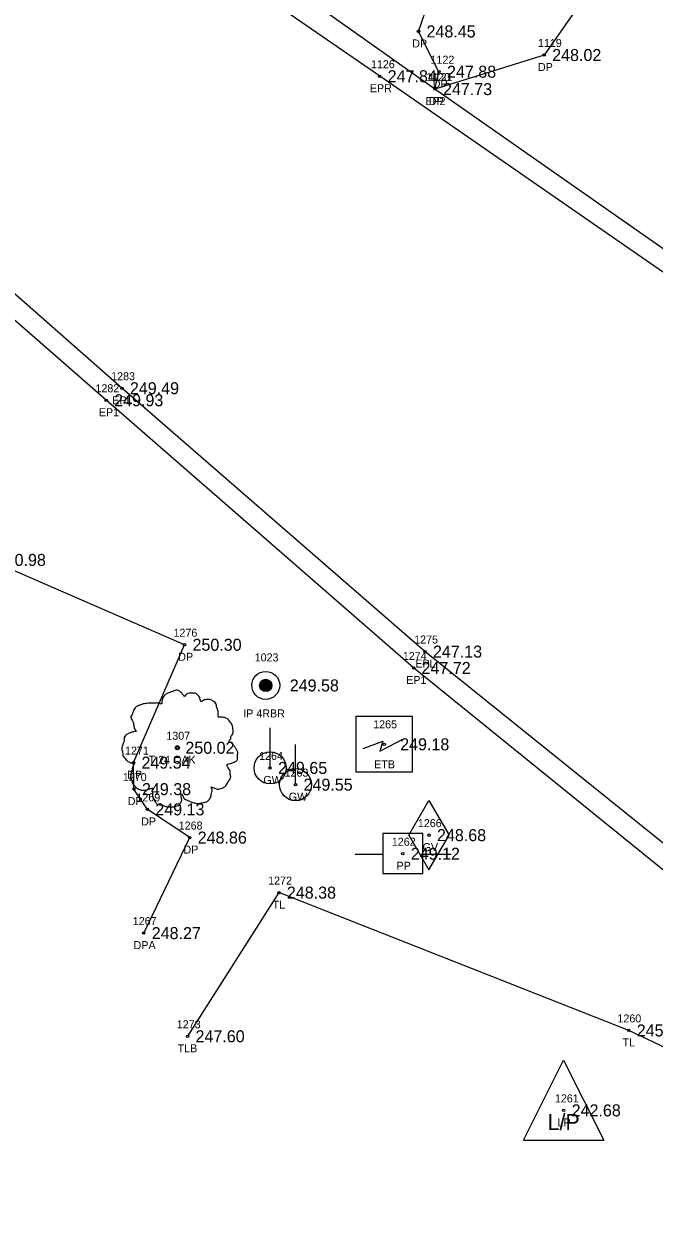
# Model space of a CAD drawing. Extents: x 1961231 to 1962574, y 799865 to 801120.
# Drawn here: x 1962101.5 to 1962180.3, y 800312.9 to 800461.9 of the extents above; entities that cross this region are included whole.
import ezdxf

# ---------------------------------------------------------------- set-up
doc = ezdxf.new("R2010")
doc.units = 0
for name, color, linetype in [('RD_EX_Driveway', 7, 'Continuous'), ('RD_EX_Driveway_txCode', 7, 'Continuous'), ('RD_EX_DV_Prop_txCode', 7, 'Continuous'), ('RD_EX_DV_PropPin', 7, 'Continuous'), ('RD_EX_Road', 7, 'Continuous'), ('RD_EX_Road_txCode', 7, 'Continuous'), ('RD_EX_TX_Driveway_ELEV', 7, 'Continuous'), ('RD_EX_TX_DV_Prop_ELEV', 7, 'Continuous'), ('RD_EX_TX_Road_ELEV', 7, 'Continuous'), ('RD_EX_TX_UT_ELEV', 7, 'Continuous'), ('RD_EX_TX_VEG_ELEV', 7, 'Continuous'), ('RD_EX_UT', 7, 'Continuous'), ('RD_EX_UT_txCode', 7, 'Continuous'), ('RD_EX_VEG', 7, 'Continuous'), ('RD_EX_VEG_txCode', 7, 'Continuous'), ('RD_HC_Survey_ELEV', 7, 'Continuous'), ('RD_SMD_Locator', 7, 'Continuous')]:
    doc.layers.add(name, color=color, linetype=linetype)

msp = doc.modelspace()

# ---------------------------------------------------------------- linework, layer by layer
at = {"layer": 'RD_EX_Driveway'}
for points in [[(1962171.38, 800493.75), (1962163.68, 800485.64), (1962177.97, 800474.42), (1962166.53, 800458.03), (1962152.89, 800453.77), (1962153.39, 800455.94), (1962150.83, 800460.97), (1962153.43, 800468.5), (1962117.51, 800493.93), (1962107.43, 800485.96)], [(1962116.51, 800348.31), (1962122.25, 800360.25), (1962116.96, 800363.77), (1962115.29, 800366.3), (1962115.23, 800369.61), (1962121.6, 800384.34), (1962097.15, 800394.94), (1962048.58, 800416.05), (1962040.61, 800398.11), (1962038.55, 800396.32), (1962035.9, 800396.16), (1962023.43, 800402.56), (1962019.98, 800406.52), (1962018.15, 800411.16)]]:
    msp.add_lwpolyline(points, dxfattribs=at)
at = {"layer": 'RD_EX_DV_PropPin'}
for p, q in [((1962131.02, 800379.07), (1962131.02, 800379.46)), ((1962131.05, 800378.97), (1962131.05, 800379.56)), ((1962131.09, 800378.9), (1962131.09, 800379.63)), ((1962131.12, 800378.84), (1962131.12, 800379.69)), ((1962131.16, 800378.79), (1962131.16, 800379.74)), ((1962131.19, 800378.75), (1962131.19, 800379.78)), ((1962131.23, 800378.71), (1962131.23, 800379.82)), ((1962131.26, 800378.68), (1962131.26, 800379.85)), ((1962131.3, 800378.66), (1962131.3, 800379.87)), ((1962131.33, 800378.63), (1962131.33, 800379.9)), ((1962131.37, 800378.61), (1962131.37, 800379.92)), ((1962131.4, 800378.59), (1962131.4, 800379.94)), ((1962131.44, 800378.57), (1962131.44, 800379.96)), ((1962131.47, 800378.56), (1962131.47, 800379.97)), ((1962131.51, 800378.54), (1962131.51, 800379.99)), ((1962131.54, 800378.53), (1962131.54, 800380)), ((1962131.58, 800378.52), (1962131.58, 800380.01)), ((1962131.61, 800378.52), (1962131.61, 800380.01)), ((1962131.65, 800378.51), (1962131.65, 800380.02)), ((1962131.68, 800378.51), (1962131.68, 800380.02)), ((1962131.72, 800378.5), (1962131.72, 800380.03)), ((1962131.75, 800378.5), (1962131.75, 800380.03)), ((1962131.79, 800378.5), (1962131.79, 800380.03)), ((1962131.82, 800378.51), (1962131.82, 800380.02)), ((1962131.86, 800378.51), (1962131.86, 800380.02)), ((1962131.89, 800378.52), (1962131.89, 800380.01)), ((1962131.93, 800378.52), (1962131.93, 800380.01)), ((1962131.96, 800378.53), (1962131.96, 800380)), ((1962132, 800378.54), (1962132, 800379.99)), ((1962132.03, 800378.56), (1962132.03, 800379.97)), ((1962132.07, 800378.57), (1962132.07, 800379.96)), ((1962132.11, 800378.59), (1962132.11, 800379.94)), ((1962132.14, 800378.61), (1962132.14, 800379.92)), ((1962132.18, 800378.63), (1962132.18, 800379.9)), ((1962132.21, 800378.66), (1962132.21, 800379.87)), ((1962132.25, 800378.68), (1962132.25, 800379.85)), ((1962132.28, 800378.71), (1962132.28, 800379.82)), ((1962132.32, 800378.75), (1962132.32, 800379.78)), ((1962132.35, 800378.79), (1962132.35, 800379.74)), ((1962132.39, 800378.84), (1962132.39, 800379.69)), ((1962132.42, 800378.9), (1962132.42, 800379.63)), ((1962132.46, 800378.97), (1962132.46, 800379.56)), ((1962132.49, 800379.07), (1962132.49, 800379.46))]:
    msp.add_line(p, q, dxfattribs=at)
for radius in [1.75, 0.761]:
    msp.add_circle((1962131.75, 800379.26), radius, dxfattribs=at)
at = {"layer": 'RD_EX_Road'}
for points in [[(1962276.74, 800366.53), (1962275.76, 800367.28), (1962226.46, 800400.66), (1962183.05, 800429.73), (1962145.98, 800455.38), (1962104.4, 800484.06), (1962056.77, 800517.94), (1962023.95, 800541.05), (1961991.87, 800563.56), (1961983.89, 800569.94), (1961938.77, 800603.67), (1961913.43, 800623.83), (1961897.73, 800636.17), (1961851.62, 800671.61), (1961815.86, 800699.48), (1961795.77, 800715.49), (1961771.88, 800733.73), (1961750.77, 800750.96), (1961735.63, 800762.82), (1961702.92, 800788.52)], [(1962241.79, 800315.68), (1962238.35, 800317.6), (1962189.92, 800352.69), (1962151.64, 800383.49), (1962113.78, 800416.39), (1962074.11, 800451.29), (1962034.78, 800486.96), (1962017.07, 800503.17), (1961999.46, 800519.25), (1961962.48, 800552.12), (1961937.08, 800573.11), (1961923.19, 800584.9), (1961883.07, 800617.43), (1961838.29, 800653.43), (1961801.42, 800682.57), (1961728.41, 800740.86), (1961722.95, 800745.11), (1961689.13, 800771.93)], [(1962275.76, 800367.28), (1962274.03, 800371.18), (1962275.17, 800373.82), (1962239.93, 800394.94), (1962227.76, 800403.12), (1962207.73, 800416.44), (1962184.45, 800431.68), (1962152.89, 800453.77), (1962107.43, 800485.96), (1962091.52, 800497.24), (1962058.28, 800520.2), (1962027.14, 800543.26), (1961995.14, 800564.69), (1961983.89, 800569.94)], [(1962238.35, 800317.6), (1962235.93, 800316.57), (1962188.31, 800350.58), (1962150.21, 800381.44), (1962111.82, 800414.89), (1962080.07, 800442.59), (1962070.81, 800442.86), (1962050.61, 800440.1), (1962031.05, 800427.32), (1962017.92, 800411.54)]]:
    msp.add_lwpolyline(points, dxfattribs=at)
at = {"layer": 'RD_EX_UT'}
for p, q in [((1962132.29, 800368.95), (1962132.29, 800373.95)), ((1962135.47, 800366.86), (1962135.47, 800371.86)), ((1962149.64, 800360.55), (1962152.14, 800364.88)), ((1962152.14, 800364.88), (1962154.64, 800360.55)), ((1962151.37, 800360.74), (1962146.37, 800360.74)), ((1962146.37, 800360.74), (1962146.37, 800355.74)), ((1962149.64, 800360.55), (1962152.14, 800356.22)), ((1962151.37, 800355.74), (1962151.37, 800360.74)), ((1962152.14, 800356.22), (1962154.64, 800360.55)), ((1962142.93, 800358.18), (1962146.4, 800358.18)), ((1962151.29, 800358.18), (1962154.93, 800358.18)), ((1962146.37, 800355.74), (1962151.37, 800355.74)), ((1962163.96, 800322.43), (1962168.96, 800332.43)), ((1962168.96, 800332.43), (1962173.96, 800322.43)), ((1962163.96, 800322.43), (1962173.96, 800322.43))]:
    msp.add_line(p, q, dxfattribs=at)
msp.add_lwpolyline([(1962143.04, 800368.4), (1962143.04, 800375.4), (1962150.04, 800375.4), (1962150.04, 800368.4)], close=True, dxfattribs=at)
msp.add_lwpolyline([(1962143.93, 800371.39), (1962146.36, 800372.29), (1962146.01, 800371.05), (1962149.06, 800372.64)], dxfattribs=at)
for centre in [(1962132.29, 800368.95), (1962135.47, 800366.86)]:
    msp.add_circle(centre, 2, dxfattribs=at)
at = {"layer": 'RD_EX_VEG'}
msp.add_lwpolyline([(1962226.08, 800312.94), (1962177.09, 800336.15), (1962133.39, 800353.37), (1962121.98, 800335.42)], dxfattribs=at)
for centre, radius in [((1962120.71, 800371.47), 0.25), ((1962120.7, 800371.45), 0.0001)]:
    msp.add_circle(centre, radius, dxfattribs=at)
for points in [[(1962120.85, 800378.64), (1962120.55, 800378.66), (1962120.22, 800378.56), (1962119.97, 800378.46), (1962119.75, 800378.39), (1962119.52, 800378.29), (1962119.22, 800378.11), (1962119, 800377.91), (1962118.87, 800377.66), (1962118.82, 800377.44), (1962118.77, 800377.16), (1962118.77, 800376.99), (1962118.65, 800376.96), (1962118.5, 800376.99), (1962118.25, 800377.06), (1962118, 800377.06), (1962117.75, 800377.06), (1962117.4, 800377.04), (1962117.05, 800377.04), (1962116.77, 800376.99), (1962116.45, 800376.94), (1962116.07, 800376.81), (1962115.72, 800376.69), (1962115.42, 800376.44), (1962115.17, 800375.96), (1962115.05, 800375.61), (1962114.9, 800375.36), (1962115.05, 800374.91), (1962115.22, 800374.56), (1962115.25, 800374.36), (1962115.32, 800373.94), (1962115.42, 800373.71), (1962115.55, 800373.51), (1962115.47, 800373.49), (1962115.1, 800373.44), (1962114.8, 800373.34), (1962114.37, 800373.11), (1962114.15, 800372.89), (1962114.05, 800372.56), (1962114.02, 800372.21), (1962113.92, 800372.01), (1962113.85, 800371.74), (1962113.82, 800371.66), (1962113.77, 800371.34), (1962113.87, 800370.89), (1962113.9, 800370.54), (1962114.02, 800370.31), (1962114.17, 800370.14), (1962114.35, 800369.89), (1962114.75, 800369.66), (1962115.07, 800369.56), (1962115.27, 800369.54), (1962115.1, 800369.04), (1962115.05, 800368.69), (1962114.92, 800368.29), (1962114.92, 800368.21), (1962114.87, 800367.74), (1962115.02, 800367.42), (1962115.1, 800367.04), (1962115.27, 800366.82), (1962115.55, 800366.52), (1962115.87, 800366.29), (1962116.37, 800366.17), (1962116.77, 800366.19), (1962117.35, 800366.37), (1962117.6, 800366.44), (1962117.57, 800366.27), (1962117.6, 800365.89), (1962117.6, 800365.47), (1962117.75, 800365.14), (1962117.85, 800364.87), (1962118, 800364.62), (1962118.32, 800364.39), (1962118.72, 800364.32), (1962119.15, 800364.17), (1962119.6, 800364.09), (1962120.1, 800364.07), (1962120.7, 800364.22), (1962120.97, 800364.34), (1962121.07, 800364.52), (1962121.27, 800364.89), (1962121.22, 800365.12), (1962121.25, 800365.72), (1962121.35, 800365.54), (1962121.52, 800365.19), (1962122.02, 800364.89), (1962122.42, 800364.72), (1962122.9, 800364.57), (1962123.2, 800364.49), (1962123.67, 800364.57), (1962124.05, 800364.64), (1962124.42, 800364.77), (1962124.72, 800365.04), (1962124.9, 800365.32), (1962124.95, 800365.59), (1962125.02, 800365.97), (1962125.07, 800366.14)], [(1962125.07, 800366.14), (1962125, 800366.32), (1962124.95, 800366.57), (1962125.02, 800366.54), (1962125.19, 800366.49), (1962125.47, 800366.37), (1962125.69, 800366.29), (1962126.02, 800366.32), (1962126.29, 800366.42), (1962126.74, 800366.69), (1962127.02, 800367.17), (1962127.29, 800367.57), (1962127.37, 800367.89), (1962127.32, 800368.11), (1962127.29, 800368.61), (1962127.09, 800368.86), (1962127.04, 800368.99), (1962126.94, 800369.39), (1962127.02, 800369.44), (1962127.29, 800369.49), (1962127.67, 800369.61), (1962127.94, 800369.74), (1962128.17, 800369.91), (1962128.24, 800370.14), (1962128.22, 800370.54), (1962128.27, 800370.94), (1962128.19, 800371.09), (1962128.09, 800371.24), (1962128.02, 800371.44), (1962127.87, 800371.59), (1962127.77, 800371.74), (1962127.67, 800371.84), (1962127.54, 800371.99), (1962127.37, 800372.11), (1962127.22, 800372.16), (1962127.17, 800372.31), (1962127.32, 800372.51), (1962127.37, 800372.61), (1962127.39, 800372.84), (1962127.62, 800373.19), (1962127.67, 800373.59), (1962127.62, 800374.01), (1962127.57, 800374.29), (1962127.42, 800374.56), (1962127.22, 800374.81), (1962127.09, 800374.99), (1962126.92, 800375.11), (1962126.59, 800375.24), (1962126.34, 800375.29), (1962125.99, 800375.29), (1962125.79, 800375.34), (1962125.82, 800375.39), (1962125.82, 800375.54), (1962125.82, 800375.81), (1962125.74, 800376.26), (1962125.59, 800376.76), (1962125.59, 800376.79), (1962125.49, 800377.04), (1962125.27, 800377.24), (1962125.09, 800377.34), (1962124.9, 800377.46), (1962124.65, 800377.49), (1962124.35, 800377.49), (1962124.07, 800377.44), (1962123.87, 800377.34), (1962123.7, 800377.21), (1962123.62, 800377.36), (1962123.52, 800377.66), (1962123.47, 800377.81), (1962123.32, 800377.99), (1962123.1, 800378.19), (1962122.65, 800378.31), (1962122.02, 800378.24), (1962121.72, 800378.04), (1962121.57, 800377.86), (1962121.52, 800377.99), (1962121.32, 800378.19), (1962121.22, 800378.36), (1962121.05, 800378.49), (1962120.9, 800378.59), (1962120.8, 800378.64)]]:
    msp.add_spline(points, degree=3, dxfattribs=at)
at = {"layer": 'RD_SMD_Locator'}
for centre in [(1962150.83, 800460.97), (1962166.53, 800458.03), (1962145.98, 800455.38), (1962153.39, 800455.94), (1962152.89, 800453.77), (1962152.89, 800453.77), (1962113.78, 800416.39), (1962111.82, 800414.89), (1962121.6, 800384.34), (1962151.64, 800383.49), (1962150.21, 800381.44), (1962131.75, 800379.26), (1962120.71, 800371.47), (1962146.54, 800371.9), (1962115.23, 800369.61), (1962132.29, 800368.95), (1962135.47, 800366.86), (1962115.29, 800366.3), (1962116.96, 800363.77), (1962122.25, 800360.25), (1962152.14, 800360.55), (1962148.87, 800358.23), (1962133.39, 800353.37), (1962116.51, 800348.31), (1962177.09, 800336.15), (1962121.98, 800335.42), (1962168.96, 800326.16)]:
    msp.add_circle(centre, 0.15, dxfattribs=at)

# ---------------------------------------------------------------- texts
at = {"layer": 'RD_EX_Driveway_txCode'}
for s, p in [('DP', (1962150.05, 800458.97)), ('1119', (1962165.75, 800459.03)), ('1122', (1962152.33, 800456.94)), ('DP', (1962165.75, 800456.03)), ('1121', (1962152.11, 800454.77)), ('DP', (1962152.61, 800453.94)), ('DP', (1962152.11, 800451.77)), ('1276', (1962120.23, 800385.34)), ('DP', (1962120.82, 800382.34)), ('1271', (1962114.17, 800370.61)), ('DP', (1962114.45, 800367.61)), ('1270', (1962113.9, 800367.3)), ('1269', (1962115.59, 800364.77)), ('DP', (1962114.51, 800364.3)), ('DP', (1962116.18, 800361.77)), ('1268', (1962120.88, 800361.25)), ('DP', (1962121.47, 800358.25)), ('1267', (1962115.14, 800349.31)), ('DPA', (1962115.24, 800346.31))]:
    msp.add_text(s, height=1, dxfattribs=at).set_placement(p)
at = {"layer": 'RD_EX_DV_Prop_txCode'}
for s, p in [('1023', (1962130.37, 800382.26)), ('IP 4RBR', (1962128.94, 800375.26))]:
    msp.add_text(s, height=1, dxfattribs=at).set_placement(p)
at = {"layer": 'RD_EX_Road_txCode'}
for s, p in [('1126', (1962144.89, 800456.38)), ('1120', (1962151.79, 800454.77)), ('EPR', (1962144.75, 800453.38)), ('EP2', (1962151.68, 800451.77)), ('1283', (1962112.44, 800417.39)), ('1282', (1962110.48, 800415.89)), ('EPL', (1962112.58, 800414.39)), ('EP1', (1962110.9, 800412.89)), ('1275', (1962150.29, 800384.49)), ('1274', (1962148.87, 800382.44)), ('EPL', (1962150.43, 800381.49)), ('EP1', (1962149.29, 800379.44))]:
    msp.add_text(s, height=1, dxfattribs=at).set_placement(p)
at = {"layer": 'RD_EX_TX_Driveway_ELEV'}
for s, p in [('248.45', (1962151.83, 800460.22)), ('248.02', (1962167.53, 800457.28)), ('247.88', (1962154.39, 800455.19)), ('247.73', (1962153.89, 800453.02)), ('250.98', (1962098.15, 800394.19)), ('250.30', (1962122.6, 800383.59)), ('249.54', (1962116.23, 800368.86)), ('249.38', (1962116.29, 800365.55)), ('249.13', (1962117.96, 800363.02)), ('248.86', (1962123.25, 800359.5)), ('248.27', (1962117.51, 800347.56))]:
    msp.add_text(s, height=1.5, dxfattribs=at).set_placement(p)
at = {"layer": 'RD_EX_TX_DV_Prop_ELEV'}
msp.add_text('249.58', height=1.5, dxfattribs=at).set_placement((1962134.75, 800378.51))
at = {"layer": 'RD_EX_TX_Road_ELEV'}
for s, p in [('247.84', (1962146.98, 800454.63)), ('247.73', (1962153.89, 800453.02)), ('249.49', (1962114.78, 800415.64)), ('249.93', (1962112.82, 800414.14)), ('247.13', (1962152.64, 800382.74)), ('247.72', (1962151.21, 800380.69))]:
    msp.add_text(s, height=1.5, dxfattribs=at).set_placement(p)
at = {"layer": 'RD_EX_TX_UT_ELEV'}
for s, p in [('249.18', (1962148.54, 800371.15)), ('249.65', (1962133.29, 800368.2)), ('249.55', (1962136.47, 800366.11)), ('248.68', (1962153.14, 800359.8)), ('242.68', (1962169.96, 800325.41))]:
    msp.add_text(s, height=1.5, dxfattribs=at).set_placement(p)
at = {"layer": 'RD_EX_TX_VEG_ELEV'}
for s, p in [('250.02', (1962121.71, 800370.72)), ('248.38', (1962134.39, 800352.62)), ('247.60', (1962122.98, 800334.67)), ('245.06', (1962178.09, 800335.4))]:
    msp.add_text(s, height=1.5, dxfattribs=at).set_placement(p)
at = {"layer": 'RD_EX_UT'}
msp.add_text('L/P', height=2, dxfattribs=at).set_placement((1962166.95, 800323.71))
at = {"layer": 'RD_EX_UT_txCode'}
for s, p in [('1265', (1962145.17, 800373.9)), ('1264', (1962130.92, 800369.95)), ('1263', (1962134.1, 800367.86)), ('ETB', (1962145.29, 800368.9)), ('GW', (1962131.45, 800366.95)), ('GW', (1962134.63, 800364.86)), ('1266', (1962150.75, 800361.55)), ('1262', (1962147.5, 800359.23)), ('GV', (1962151.34, 800358.55)), ('PP', (1962148.09, 800356.23)), ('1261', (1962167.87, 800327.16)), ('LP', (1962168.2, 800324.16))]:
    msp.add_text(s, height=1, dxfattribs=at).set_placement(p)
at = {"layer": 'RD_EX_VEG_txCode'}
for s, p in [('1307', (1962119.33, 800372.47)), ('T 24 OAK', (1962117.13, 800369.47)), ('1272', (1962132.05, 800354.37)), ('TL', (1962132.62, 800351.37)), ('1273', (1962120.64, 800336.42)), ('1260', (1962175.68, 800337.15)), ('TLB', (1962120.74, 800333.42)), ('TL', (1962176.31, 800334.15))]:
    msp.add_text(s, height=1, dxfattribs=at).set_placement(p)
at = {"layer": 'RD_HC_Survey_ELEV'}
msp.add_text('249.12', height=1.5, dxfattribs=at).set_placement((1962149.87, 800357.48))

doc.saveas('drawing.dxf')
